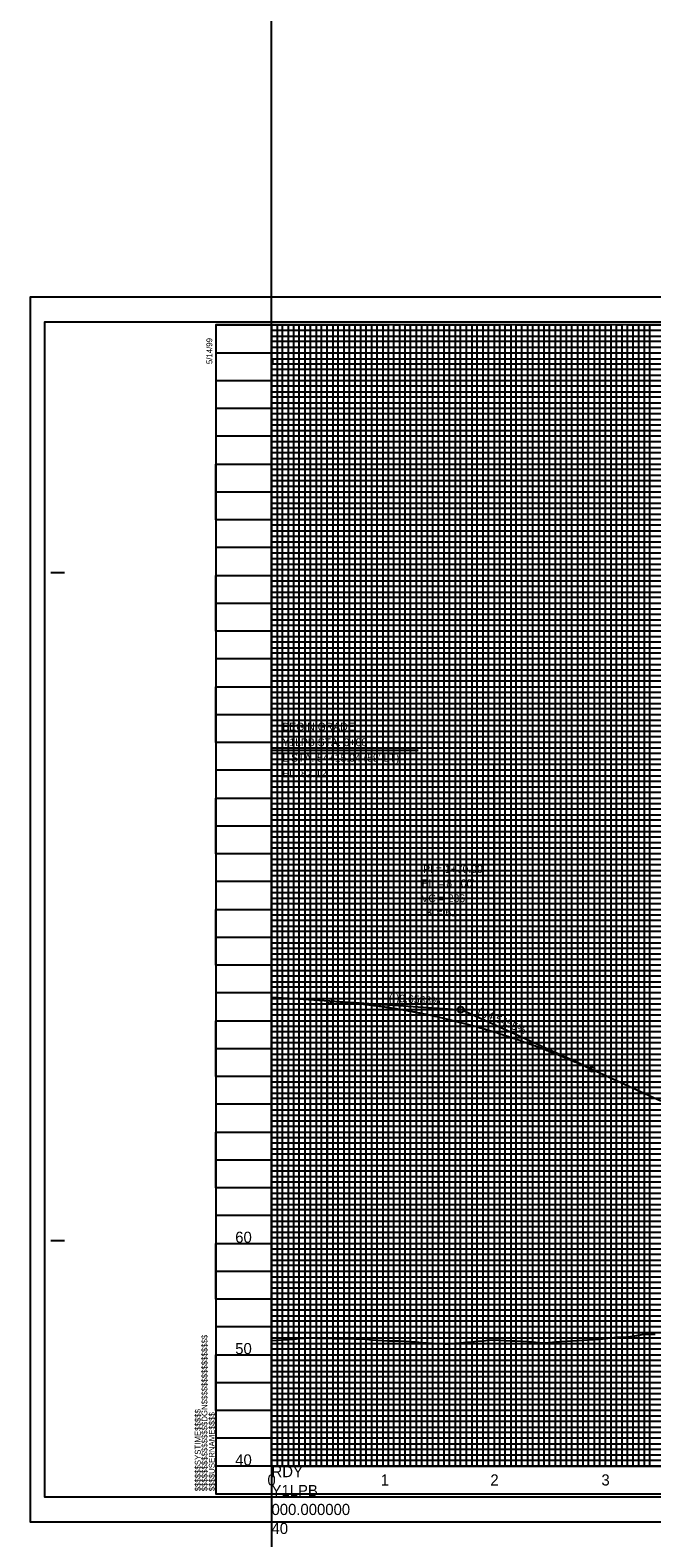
# Model space of a CAD drawing. Extents: x 2345490 to 2436403, y 465165 to 573888.
# Drawn here: x 2410678 to 2411237, y 514167 to 515521 of the extents above; entities that cross this region are included whole.
import ezdxf

# ---------------------------------------------------------------- set-up
doc = ezdxf.new("R2010")
doc.units = 0
for name, color, linetype in [('Old_Level_1', 7, 'Continuous'), ('Old_Level_18', 7, 'Continuous'), ('Old_Level_2', 7, 'Continuous'), ('Old_Level_40', 7, 'Continuous'), ('Old_Level_41', 7, 'Continuous'), ('Old_Level_42', 7, 'Continuous'), ('Old_Level_43', 7, 'Continuous'), ('Old_Level_50', 7, 'Continuous'), ('Old_Level_51', 7, 'Continuous'), ('Old_Level_52', 7, 'Continuous'), ('Old_Level_63', 7, 'Continuous')]:
    doc.layers.add(name, color=color, linetype=linetype)

msp = doc.modelspace()

# ---------------------------------------------------------------- linework, layer by layer
at = {"layer": 'Old_Level_1'}
msp.add_lwpolyline([(2410895.325, 514343.83425), (2410900.325, 514344.205), (2410905.325, 514344.5755), (2410910.325, 514344.946), (2410915.325, 514345.31625), (2410920.325, 514345.67525), (2410925.325, 514345.957), (2410930.325, 514346.239), (2410935.325, 514346.21925), (2410940.325, 514346.11375), (2410945.325, 514346.0085), (2410950.325, 514345.903), (2410955.325, 514345.79725), (2410960.325, 514345.6915), (2410965.325, 514345.6435), (2410970.325, 514345.5985), (2410975.325, 514345.34475), (2410980.325, 514345.033), (2410985.325, 514344.72075), (2410990.325, 514344.408), (2410995.325, 514344.0945), (2411000.325, 514343.7805), (2411005.325, 514343.5385), (2411010.325, 514343.5925), (2411015.325, 514343.3525), (2411020.325, 514343.00225), (2411025.325, 514342.6465), (2411030.325, 514342.2845), (2411035.325, 514341.91625), (2411040.325, 514341.54175), (2411045.325, 514341.16075), (2411050.325, 514340.8715), (2411055.325, 514340.95525), (2411060.325, 514341.45325), (2411065.325, 514341.943), (2411070.325, 514342.4245), (2411075.325, 514342.89725), (2411080.325, 514343.36075), (2411085.325, 514343.81475), (2411090.325, 514344.25875), (2411095.325, 514344.5955), (2411100.325, 514344.337), (2411105.325, 514344.07375), (2411110.325, 514343.8055), (2411115.325, 514343.5325), (2411120.325, 514343.255), (2411125.325, 514342.973), (2411130.325, 514342.6475), (2411135.325, 514342.2805), (2411140.325, 514341.95825), (2411145.325, 514342.313), (2411150.325, 514342.667), (2411155.325, 514343.0165), (2411160.325, 514343.359), (2411165.325, 514343.694), (2411170.325, 514344.02175), (2411175.325, 514344.34175), (2411180.325, 514344.654), (2411185.325, 514344.95825), (2411190.325, 514345.25475), (2411195.325, 514345.75825), (2411200.325, 514346.33375), (2411205.325, 514346.85525), (2411210.325, 514347.0715), (2411215.325, 514347.269), (2411220.325, 514347.81775), (2411225.325, 514348.8045), (2411230.325, 514349.765), (2411235.325, 514349.732), (2411240.325, 514349.688)], dxfattribs=at)
at = {"layer": 'Old_Level_18'}
msp.add_line((2410845.325, 514206.21425), (2410845.325, 514206.21425), dxfattribs=at)
msp.add_line((2410845.325, 514206.21425), (2410845.325, 514206.21425), dxfattribs=at)
msp.add_lwpolyline([(2412345.325, 515256.21425), (2410845.325, 515256.21425), (2410845.325, 514206.21425), (2412345.325, 514206.21425)], close=True, dxfattribs=at)
at = {"layer": 'Old_Level_2'}
for p, q in [((2410895.325, 514873.8145), (2410895.325, 514652.4145)), ((2411027.162, 514873.8145), (2410895.325, 514873.8145)), ((2410895.325, 514652.4145), (2410947.325, 514648.98875)), ((2410947.325, 514648.98875), (2411062.581, 514641.3955)), ((2411183.325, 514587.57825), (2411067.82875, 514640.07675)), ((2411183.325, 514587.57825), (2411245.325, 514559.3965))]:
    msp.add_line(p, q, dxfattribs=at)
for centre, radius in [((2410947.325, 514648.98875), 2.25), ((2411065.325, 514641.2145), 2.75), ((2411183.325, 514587.57825), 2.25)]:
    msp.add_circle(centre, radius, dxfattribs=at)
msp.add_spline([(2410947.325, 514648.98875), (2410952.045, 514648.6595), (2410956.765, 514648.2935), (2410961.485, 514647.89075), (2410966.205, 514647.45125), (2410970.925, 514646.97525), (2410975.645, 514646.4625), (2410980.365, 514645.913), (2410985.085, 514645.327), (2410989.805, 514644.704), (2410994.525, 514644.0445), (2410999.245, 514643.3485), (2411003.965, 514642.6155), (2411008.685, 514641.846), (2411013.405, 514641.03975), (2411018.125, 514640.19675), (2411022.845, 514639.317), (2411027.565, 514638.40075), (2411032.285, 514637.44775), (2411037.005, 514636.458), (2411041.725, 514635.4315), (2411046.445, 514634.3685), (2411051.165, 514633.2685), (2411055.885, 514632.132), (2411060.605, 514630.959), (2411065.325, 514629.749), (2411070.045, 514628.5025), (2411074.765, 514627.21925), (2411079.485, 514625.89925), (2411084.205, 514624.54275), (2411088.925, 514623.1495), (2411093.645, 514621.7195), (2411098.365, 514620.25275), (2411103.085, 514618.74925), (2411107.805, 514617.20925), (2411112.525, 514615.6325), (2411117.245, 514614.019), (2411121.965, 514612.369), (2411126.685, 514610.682), (2411131.405, 514608.9585), (2411136.125, 514607.19825), (2411140.845, 514605.4015), (2411145.565, 514603.56775), (2411150.285, 514601.6975), (2411155.005, 514599.7905), (2411159.725, 514597.847), (2411164.445, 514595.8665), (2411169.165, 514593.8495), (2411173.885, 514591.79575), (2411178.605, 514589.70525), (2411183.325, 514587.57825)], degree=3, dxfattribs=at)
at = {"layer": 'Old_Level_40'}
msp.add_line((2410845.325, 514206.21425), (2410845.325, 514206.21425), dxfattribs=at)
msp.add_line((2410845.325, 514206.21425), (2410845.325, 514206.21425), dxfattribs=at)
msp.add_line((2410845.325, 514206.21425), (2410845.325, 514206.21425), dxfattribs=at)
msp.add_line((2410845.325, 514206.21425), (2410845.325, 514206.21425), dxfattribs=at)
at = {"layer": 'Old_Level_41'}
for p, q in [((2410696.825, 515033.71425), (2410709.325, 515033.71425)), ((2410696.825, 514433.71425), (2410709.325, 514433.71425)), ((2412345.325, 514231.21425), (2410845.325, 514231.21425))]:
    msp.add_line(p, q, dxfattribs=at)
for points in [[(2410845.325, 515256.21425), (2410895.325, 515256.21425), (2410895.325, 514231.21425), (2410945.325, 514231.21425), (2410945.325, 515256.21425), (2410995.325, 515256.21425), (2410995.325, 514231.21425), (2411045.325, 514231.21425), (2411045.325, 515256.21425), (2411095.325, 515256.21425), (2411095.325, 514231.21425), (2411145.325, 514231.21425), (2411145.325, 515256.21425), (2411195.325, 515256.21425), (2411195.325, 514231.21425), (2411245.325, 514231.21425)], [(2410920.325, 514231.21425), (2410920.325, 515256.21425), (2410970.325, 515256.21425), (2410970.325, 514231.21425), (2411020.325, 514231.21425), (2411020.325, 515256.21425), (2411070.325, 515256.21425), (2411070.325, 514231.21425), (2411120.325, 514231.21425), (2411120.325, 515256.21425), (2411170.325, 515256.21425), (2411170.325, 514231.21425), (2411220.325, 514231.21425), (2411220.325, 515256.21425), (2411270.325, 515256.21425)], [(2410845.325, 515206.21425), (2412145.275, 515206.21425)], [(2412145.275, 515156.21425), (2410845.325, 515156.21425), (2410845.325, 515106.16425), (2412345.325, 515106.16425)], [(2412345.325, 515081.21425), (2410845.325, 515081.21425), (2410845.325, 515131.21425), (2412145.275, 515131.21425)], [(2412345.325, 515056.21425), (2410845.325, 515056.21425), (2410845.325, 515006.21425), (2412345.325, 515006.21425)], [(2412345.325, 514981.21425), (2410845.325, 514981.21425), (2410845.325, 515031.21425), (2412345.325, 515031.21425)], [(2412345.325, 514956.21425), (2410845.325, 514956.21425), (2410845.325, 514906.21425), (2412345.325, 514906.21425)], [(2412345.325, 514856.21425), (2410845.325, 514856.21425), (2410845.325, 514806.21425), (2412345.325, 514806.21425)], [(2412345.325, 514756.21425), (2410845.325, 514756.21425), (2410845.325, 514706.21425), (2412345.325, 514706.21425)], [(2412345.325, 514656.21425), (2410845.325, 514656.21425), (2410845.325, 514606.21425), (2412345.325, 514606.21425)], [(2412345.325, 514581.21425), (2410845.325, 514581.21425), (2410845.325, 514631.21425), (2412345.325, 514631.21425)], [(2412345.325, 514556.21425), (2410845.325, 514556.21425), (2410845.325, 514506.21425), (2412345.325, 514506.21425)], [(2412345.325, 514481.21425), (2410845.325, 514481.21425), (2410845.325, 514531.21425), (2412345.325, 514531.21425)], [(2412345.325, 514456.21425), (2410845.325, 514456.21425), (2410845.325, 514406.21425), (2412345.325, 514406.21425)], [(2412345.325, 514356.21425), (2410845.325, 514356.21425), (2410845.325, 514306.21425), (2412345.325, 514306.21425)], [(2412345.325, 514281.21425), (2410845.325, 514281.21425), (2410845.325, 514331.21425), (2412345.325, 514331.21425)], [(2412345.325, 514256.21425), (2410845.325, 514256.21425)], [(2410882.825, 514206.21425), (2410882.825, 514206.21425)]]:
    msp.add_lwpolyline(points, dxfattribs=at)
at = {"layer": 'Old_Level_42'}
for points in [[(2412145.275, 515181.21425), (2410845.425, 515181.21425), (2410845.425, 515231.16425), (2412145.275, 515231.16425)], [(2412345.325, 514881.21425), (2410845.325, 514881.21425), (2410845.325, 514931.21425), (2412345.325, 514931.21425)], [(2412345.325, 514781.21425), (2410845.325, 514781.21425), (2410845.325, 514831.21425), (2412345.325, 514831.21425)], [(2412345.325, 514681.21425), (2410845.325, 514681.21425), (2410845.325, 514731.21425), (2412345.325, 514731.21425)], [(2412345.325, 514381.21425), (2410845.325, 514381.21425), (2410845.325, 514431.21425), (2412345.325, 514431.21425)]]:
    msp.add_lwpolyline(points, dxfattribs=at)
at = {"layer": 'Old_Level_43'}
for p, q in [((2412295.325, 515076.21425), (2410895.325, 515076.21425)), ((2410895.325, 515076.21425), (2410895.325, 515071.21425)), ((2410895.325, 515071.21425), (2412295.325, 515071.21425)), ((2412295.325, 515051.21425), (2410895.325, 515051.21425))]:
    msp.add_line(p, q, dxfattribs=at)
for points in [[(2410900.325, 515256.21425), (2410905.325, 515256.21425), (2410910.325, 515256.21425), (2410915.325, 515256.21425), (2410925.325, 515256.21425), (2410892.275, 515256.21425), (2410897.275, 515256.21425), (2410855.325, 515256.21425), (2410860.325, 515256.21425), (2410865.325, 515256.21425), (2410875.325, 515256.21425), (2410880.325, 515256.21425), (2410885.325, 515256.21425), (2410890.325, 515256.21425), (2410900.325, 515256.21425), (2410900.325, 514231.21425), (2410905.325, 514231.21425), (2410905.325, 515256.21425), (2410910.325, 515256.21425), (2410910.325, 514231.21425), (2410915.325, 514231.21425), (2410915.325, 515256.21425), (2410925.325, 515256.21425), (2410925.325, 514231.21425), (2410930.325, 514231.21425), (2410930.325, 515256.21425), (2410935.325, 515256.21425), (2410935.325, 514231.21425), (2410940.325, 514231.21425), (2410940.325, 515256.21425), (2410950.325, 515256.21425), (2410950.325, 514231.21425), (2410955.325, 514231.21425), (2410955.325, 515256.21425), (2410960.325, 515256.21425), (2410960.325, 514231.21425), (2410965.325, 514231.21425), (2410965.325, 515256.21425), (2410975.325, 515256.21425), (2410975.325, 514231.21425), (2410980.325, 514231.21425), (2410980.325, 515256.21425), (2410985.325, 515256.21425), (2410985.325, 514231.21425), (2410990.325, 514231.21425), (2410990.325, 515256.21425), (2411000.325, 515256.21425), (2411000.325, 514231.21425), (2411005.325, 514231.21425), (2411005.325, 515256.21425), (2411010.325, 515256.21425), (2411010.325, 514231.21425), (2411015.325, 514231.21425), (2411015.325, 515256.21425), (2411025.325, 515256.21425), (2411025.325, 514231.21425), (2411030.325, 514231.21425), (2411030.325, 515256.21425), (2411035.325, 515256.21425), (2411035.325, 514231.21425), (2411040.325, 514231.21425), (2411040.325, 515256.21425), (2411050.325, 515256.21425), (2411050.325, 514231.21425), (2411055.325, 514231.21425), (2411055.325, 515256.21425), (2411060.325, 515256.21425), (2411060.325, 514231.21425)], [(2412145.275, 515251.21425), (2410895.325, 515251.21425), (2410895.325, 515246.21425), (2412145.275, 515246.21425)], [(2411060.325, 514231.21425), (2411065.325, 514231.21425), (2411065.325, 515256.21425), (2411075.325, 515256.21425), (2411075.325, 514231.21425), (2411080.325, 514231.21425), (2411080.325, 515256.21425), (2411085.325, 515256.21425), (2411085.325, 514231.21425), (2411090.325, 514231.21425), (2411090.325, 515256.21425), (2411100.325, 515256.21425), (2411100.325, 514231.21425), (2411105.325, 514231.21425), (2411105.325, 515256.21425), (2411105.325, 515256.21425), (2411110.325, 515256.21425), (2411110.325, 514231.21425), (2411115.325, 514231.21425), (2411115.325, 515256.21425), (2411125.325, 515256.21425), (2411125.325, 514231.21425), (2411130.325, 514231.21425), (2411130.325, 515256.21425), (2411135.325, 515256.21425), (2411135.325, 514231.21425), (2411140.325, 514231.21425), (2411140.325, 515256.21425), (2411150.325, 515256.21425), (2411150.325, 514231.21425), (2411155.325, 514231.21425), (2411155.325, 515256.21425), (2411160.325, 515256.21425), (2411160.325, 514231.21425), (2411165.325, 514231.21425), (2411165.325, 515256.21425), (2411175.325, 515256.21425), (2411175.325, 514231.21425), (2411180.325, 514231.21425), (2411180.325, 515256.21425), (2411185.325, 515256.21425), (2411185.325, 514231.21425), (2411190.325, 514231.21425), (2411190.325, 515256.21425), (2411200.325, 515256.21425), (2411200.325, 514231.21425), (2411205.325, 514231.21425), (2411205.325, 515256.21425), (2411210.325, 515256.21425), (2411210.325, 514231.21425), (2411215.325, 514231.21425), (2411215.325, 515256.21425), (2411225.325, 515256.21425), (2411225.325, 514231.21425), (2411240.325, 514231.21425)], [(2411230.325, 515256.21425), (2411230.325, 514231.21425), (2411235.325, 514231.21425), (2411235.325, 515256.21425)], [(2411230.325, 515255.61425), (2411230.325, 514231.21425), (2411235.325, 514231.21425), (2411235.325, 515255.61425)], [(2412145.275, 515241.21425), (2410895.325, 515241.21425), (2410895.325, 515236.21425), (2412145.275, 515236.21425)], [(2412145.275, 515225.46425), (2410896.325, 515225.46425), (2410896.325, 515221.21425), (2412145.275, 515221.21425)], [(2412145.275, 515216.21425), (2410895.325, 515216.21425), (2410895.325, 515211.21425), (2412145.275, 515211.21425)], [(2412145.275, 515201.21425), (2410895.325, 515201.21425), (2410895.325, 515196.21425), (2412145.275, 515196.21425)], [(2412145.275, 515191.21425), (2410895.325, 515191.21425), (2410895.325, 515186.21425), (2412145.275, 515186.21425)], [(2412145.275, 515176.21425), (2410895.325, 515176.21425), (2410895.325, 515171.21425), (2412145.275, 515171.21425)], [(2412145.275, 515166.21425), (2410895.325, 515166.21425), (2410895.325, 515161.21425), (2412145.275, 515161.21425)], [(2412145.275, 515151.21425), (2410895.325, 515151.21425), (2410895.325, 515146.21425), (2412145.275, 515146.21425)], [(2412145.275, 515141.21425), (2410895.325, 515141.21425), (2410895.325, 515136.21425), (2412145.275, 515136.21425)], [(2412145.275, 515126.21425), (2410895.325, 515126.21425), (2410895.325, 515121.21425), (2412145.275, 515121.21425)], [(2412295.325, 515116.21425), (2410895.325, 515116.21425), (2410895.325, 515116.21425), (2410895.325, 515096.21425), (2412295.325, 515096.21425)], [(2410895.325, 515111.21425), (2412295.325, 515111.21425)], [(2412295.325, 515101.21425), (2410895.325, 515101.21425)], [(2412295.325, 515091.21425), (2410895.325, 515091.21425), (2410895.325, 515086.21425), (2412295.325, 515086.21425)], [(2412295.325, 515066.21425), (2410895.325, 515066.21425), (2410895.325, 515061.21425), (2412295.325, 515061.21425)], [(2412295.325, 515046.21425), (2410895.325, 515046.21425), (2410895.325, 515041.21425), (2412295.325, 515041.21425)], [(2412295.325, 515036.21425), (2410895.325, 515036.21425)], [(2410895.325, 515026.21425), (2412295.325, 515026.21425)], [(2412295.325, 515021.21425), (2410895.325, 515021.21425), (2410895.325, 515016.21425), (2412295.325, 515016.21425)], [(2412295.325, 515011.21425), (2410895.325, 515011.21425), (2410895.325, 515001.21425), (2412295.325, 515001.21425)], [(2412295.325, 514996.21425), (2410895.325, 514996.21425), (2410895.325, 514991.21425), (2412295.325, 514991.21425)], [(2412295.325, 514986.21425), (2410895.325, 514986.21425), (2410895.325, 514976.21425), (2412295.325, 514976.21425)], [(2412295.325, 514971.21425), (2410895.325, 514971.21425), (2410895.325, 514966.21425), (2412295.325, 514966.21425)], [(2412295.325, 514961.21425), (2410895.325, 514961.21425), (2410895.325, 514951.21425), (2412295.325, 514951.21425)], [(2412295.325, 514946.21425), (2410895.325, 514946.21425), (2410895.325, 514941.21425), (2412295.325, 514941.21425)], [(2412295.325, 514936.21425), (2410895.325, 514936.21425), (2410895.325, 514926.21425), (2412295.325, 514926.21425)], [(2412295.325, 514921.21425), (2410895.325, 514921.21425), (2410895.325, 514916.21425), (2412295.325, 514916.21425)], [(2412295.325, 514911.21425), (2410895.325, 514911.21425), (2410895.325, 514901.21425), (2412295.325, 514901.21425)], [(2412295.325, 514896.21425), (2410895.325, 514896.21425), (2410895.325, 514891.21425), (2412295.325, 514891.21425)], [(2412295.325, 514886.21425), (2410895.325, 514886.21425), (2410895.325, 514876.21425), (2412295.325, 514876.21425)], [(2412295.325, 514871.21425), (2410895.325, 514871.21425), (2410895.325, 514866.21425), (2412295.325, 514866.21425)], [(2412295.325, 514861.21425), (2410895.325, 514861.21425), (2410895.325, 514851.21425), (2412295.325, 514851.21425)], [(2412295.325, 514846.21425), (2410895.325, 514846.21425), (2410895.325, 514841.21425), (2412295.325, 514841.21425)], [(2412295.325, 514836.21425), (2410895.325, 514836.21425), (2410895.325, 514826.21425), (2412295.325, 514826.21425)], [(2412295.325, 514821.21425), (2410895.325, 514821.21425), (2410895.325, 514816.21425), (2412295.325, 514816.21425)], [(2412295.325, 514811.21425), (2410895.325, 514811.21425), (2410895.325, 514801.21425), (2412295.325, 514801.21425)], [(2412295.325, 514796.21425), (2410895.325, 514796.21425), (2410895.325, 514791.21425), (2412295.325, 514791.21425)], [(2412295.325, 514786.21425), (2410895.325, 514786.21425), (2410895.325, 514776.21425), (2412295.325, 514776.21425)], [(2412295.325, 514771.21425), (2410895.325, 514771.21425), (2410895.325, 514766.21425), (2412295.325, 514766.21425)], [(2412295.325, 514761.21425), (2410895.325, 514761.21425), (2410895.325, 514751.21425), (2412295.325, 514751.21425)], [(2412295.325, 514746.21425), (2410895.325, 514746.21425), (2410895.325, 514741.21425), (2412295.325, 514741.21425)], [(2412295.325, 514736.21425), (2410895.325, 514736.21425)], [(2410895.325, 514726.21425), (2412295.325, 514726.21425)], [(2412295.325, 514721.21425), (2410895.325, 514721.21425), (2410895.325, 514716.21425), (2412295.325, 514716.21425)], [(2412295.325, 514711.21425), (2410895.325, 514711.21425), (2410895.325, 514701.21425), (2412295.325, 514701.21425)], [(2412295.325, 514696.21425), (2410895.325, 514696.21425), (2410895.325, 514691.21425), (2412295.325, 514691.21425)], [(2412295.325, 514686.21425), (2410895.325, 514686.21425), (2410895.325, 514676.21425), (2412295.325, 514676.21425)], [(2412295.325, 514671.21425), (2410895.325, 514671.21425), (2410895.325, 514666.21425), (2412295.325, 514666.21425)], [(2412295.325, 514661.21425), (2410895.325, 514661.21425), (2410895.325, 514651.21425), (2412295.325, 514651.21425)], [(2412295.325, 514646.21425), (2410895.325, 514646.21425), (2410895.325, 514641.21425), (2412295.325, 514641.21425)], [(2412295.325, 514636.21425), (2410895.325, 514636.21425), (2410895.325, 514626.21425), (2412295.325, 514626.21425)], [(2412295.325, 514621.21425), (2410895.325, 514621.21425), (2410895.325, 514616.21425), (2412295.325, 514616.21425)], [(2412295.325, 514611.21425), (2410895.325, 514611.21425), (2410895.325, 514601.21425), (2412295.325, 514601.21425)], [(2412295.325, 514596.21425), (2410895.325, 514596.21425), (2410895.325, 514591.21425), (2412295.325, 514591.21425)], [(2412295.325, 514586.21425), (2410895.325, 514586.21425), (2410895.325, 514576.21425), (2412295.325, 514576.21425)], [(2412295.325, 514571.21425), (2410895.325, 514571.21425), (2410895.325, 514566.21425), (2412295.325, 514566.21425)], [(2412295.325, 514561.21425), (2410895.325, 514561.21425), (2410895.325, 514551.21425), (2412295.325, 514551.21425)], [(2412295.325, 514546.21425), (2410895.325, 514546.21425), (2410895.325, 514541.21425), (2412295.325, 514541.21425)], [(2412295.325, 514536.21425), (2410895.325, 514536.21425), (2410895.325, 514526.21425), (2412295.325, 514526.21425)], [(2412295.325, 514521.21425), (2410895.325, 514521.21425), (2410895.325, 514516.21425), (2412295.325, 514516.21425)], [(2412295.325, 514511.21425), (2410895.325, 514511.21425), (2410895.325, 514501.21425), (2412295.325, 514501.21425)], [(2412295.325, 514496.21425), (2410895.325, 514496.21425), (2410895.325, 514491.21425), (2412295.325, 514491.21425)], [(2412295.325, 514486.21425), (2410895.325, 514486.21425), (2410895.325, 514476.21425), (2412295.325, 514476.21425)], [(2412295.325, 514471.21425), (2410895.325, 514471.21425), (2410895.325, 514466.21425), (2412295.325, 514466.21425)], [(2412295.325, 514461.21425), (2410895.325, 514461.21425), (2410895.325, 514451.21425), (2412295.325, 514451.21425)], [(2412295.325, 514446.21425), (2410895.325, 514446.21425), (2410895.325, 514441.21425), (2412295.325, 514441.21425)], [(2412295.325, 514436.21425), (2410895.325, 514436.21425)], [(2410895.325, 514426.21425), (2412295.325, 514426.21425)], [(2412295.325, 514421.21425), (2410895.325, 514421.21425), (2410895.325, 514416.21425), (2412295.325, 514416.21425)], [(2412295.325, 514411.21425), (2410895.325, 514411.21425)], [(2410895.325, 514401.21425), (2412295.325, 514401.21425)], [(2412295.325, 514396.21425), (2410895.325, 514396.21425), (2410895.325, 514391.21425), (2412295.325, 514391.21425)], [(2412295.325, 514386.21425), (2410895.325, 514386.21425), (2410895.325, 514376.21425), (2412295.325, 514376.21425)], [(2412295.325, 514371.21425), (2410895.325, 514371.21425), (2410895.325, 514366.21425), (2412295.325, 514366.21425)], [(2412295.325, 514361.21425), (2410895.325, 514361.21425), (2410895.325, 514351.21425), (2412295.325, 514351.21425)], [(2412295.325, 514346.21425), (2410895.325, 514346.21425), (2410895.325, 514341.21425), (2412295.325, 514341.21425)], [(2412295.325, 514336.21425), (2410895.325, 514336.21425), (2410895.325, 514326.21425), (2412295.325, 514326.21425)], [(2412295.325, 514321.21425), (2410895.325, 514321.21425), (2410895.325, 514316.21425), (2412295.325, 514316.21425)], [(2412295.325, 514311.21425), (2410895.325, 514311.21425), (2410895.325, 514301.21425), (2412295.325, 514301.21425)], [(2412295.325, 514296.21425), (2410895.325, 514296.21425), (2410895.325, 514291.21425), (2412295.325, 514291.21425)], [(2412295.325, 514286.21425), (2410895.325, 514286.21425), (2410895.325, 514276.21425), (2412295.325, 514276.21425)], [(2412295.325, 514271.21425), (2410895.325, 514271.21425), (2410895.325, 514266.21425), (2412295.325, 514266.21425)], [(2412295.325, 514261.21425), (2410895.325, 514261.21425), (2410895.325, 514251.21425), (2412295.325, 514251.21425)], [(2412295.325, 514246.21425), (2410895.325, 514246.21425), (2410895.325, 514241.21425), (2412295.325, 514241.21425)], [(2412295.325, 514236.21425), (2410895.325, 514236.21425)]]:
    msp.add_lwpolyline(points, dxfattribs=at)
at = {"layer": 'Old_Level_50'}
msp.add_line((2410678.325, 514181.21425), (2410678.325, 514181.21425), dxfattribs=at)
msp.add_lwpolyline([(2412357.825, 515258.76425), (2410691.325, 515258.76425), (2410691.325, 514203.66425), (2412357.825, 514203.66425)], close=True, dxfattribs=at)
at = {"layer": 'Old_Level_51'}
msp.add_lwpolyline([(2412362.325, 515281.21425), (2410678.325, 515281.21425), (2410678.325, 514181.21425), (2412362.325, 514181.21425)], close=True, dxfattribs=at)
at = {"layer": 'Old_Level_52'}
msp.add_line((2410691.325, 514203.66425), (2410691.325, 514203.66425), dxfattribs=at)
at = {"layer": 'Old_Level_63'}
for p, q in [((2410895.325, 514231.21425), (2410895.325, 516731.21425)), ((2411045.325, 514636.25425), (2411045.325, 514860.3775)), ((2411095.325, 514623.77425), (2411095.325, 514860.3775)), ((2410895.325, 514652.41425), (2410895.325, 514435.13175)), ((2410945.325, 514649.12425), (2410945.325, 514435.13175)), ((2410995.325, 514643.93425), (2410995.325, 514435.13175)), ((2411045.325, 514632.77425), (2411045.325, 514435.13175)), ((2411095.325, 514614.39425), (2411095.325, 514435.13175)), ((2410895.325, 514231.21425), (2412358.114, 514231.21425)), ((2410895.325, 514231.21425), (2410895.325, 511731.21425))]:
    msp.add_line(p, q, dxfattribs=at)

# ---------------------------------------------------------------- texts
at = {"layer": 'Old_Level_1'}
for s, height, p in [('60', 10.000001, (2410862.7115, 514431.7145)), ('50', 10.000001, (2410862.7115, 514331.7145)), ('40', 10.000001, (2410862.7115, 514231.7145)), ('0', 10, (2410891.666, 514213.7145)), ('1', 10, (2410993.5055, 514213.7145)), ('2', 10, (2411092.054, 514213.7145)), ('3', 10, (2411191.88875, 514213.7145))]:
    msp.add_text(s, height=height, dxfattribs=at).set_placement(p)
at = {"layer": 'Old_Level_2'}
for s, height, p in [('BEGIN GRADE', 7.0000005, (2410905.06425, 514891.83875)), ('Y1LPB STA. 0+00', 7.0000005, (2410905.06425, 514877.83875)), ("L STA. 54+15.04 (59' LT)", 7.0000005, (2410905.06425, 514863.83875)), ('EL. 82.12', 7.000001, (2410905.06425, 514849.83875)), ('PI = 1+70.00', 7.0000005, (2411031.65425, 514763.90275)), ("EL = 81.00'", 7.0000005, (2411030.325, 514751.2145)), ("VC = 236'", 7.000001, (2411030.04225, 514737.70175)), ('K = 61', 7.000001, (2411034.87825, 514724.9895))]:
    msp.add_text(s, height=height, dxfattribs=at).set_placement(p)
for s, rotation, p in [('(-)0.6588%', 356.23066667, (2411000.6985, 514648.47925)), ('(-)4.5455%', 335.55604444, (2411080.1545, 514637.7695))]:
    msp.add_text(s, height=7.000001, rotation=rotation, dxfattribs=at).set_placement(p)
at = {"layer": 'Old_Level_41'}
for s, p in [('5/14/99', (2410842.075, 515221.01425)), ('$$$$$$$$$$$$$$$$DGN$$$$$$$$$$$$$$$$', (2410837.675, 514208.57675)), ('$$$$$$SYSTIME$$$$$', (2410831.625, 514208.57675)), ('$$$$USERNAME$$$$', (2410844.25, 514208.58925))]:
    msp.add_text(s, height=5.25, rotation=90, dxfattribs=at).set_placement(p)
at = {"layer": 'Old_Level_63'}
for s, p in [('RDY', (2410895.325, 514221.21425)), ('Y1LPB', (2410895.325, 514204.21425)), ('000.000000', (2410895.325, 514187.21425)), ('40', (2410895.325, 514170.21425))]:
    msp.add_text(s, height=10.000001, dxfattribs=at).set_placement(p)

doc.saveas('drawing.dxf')
